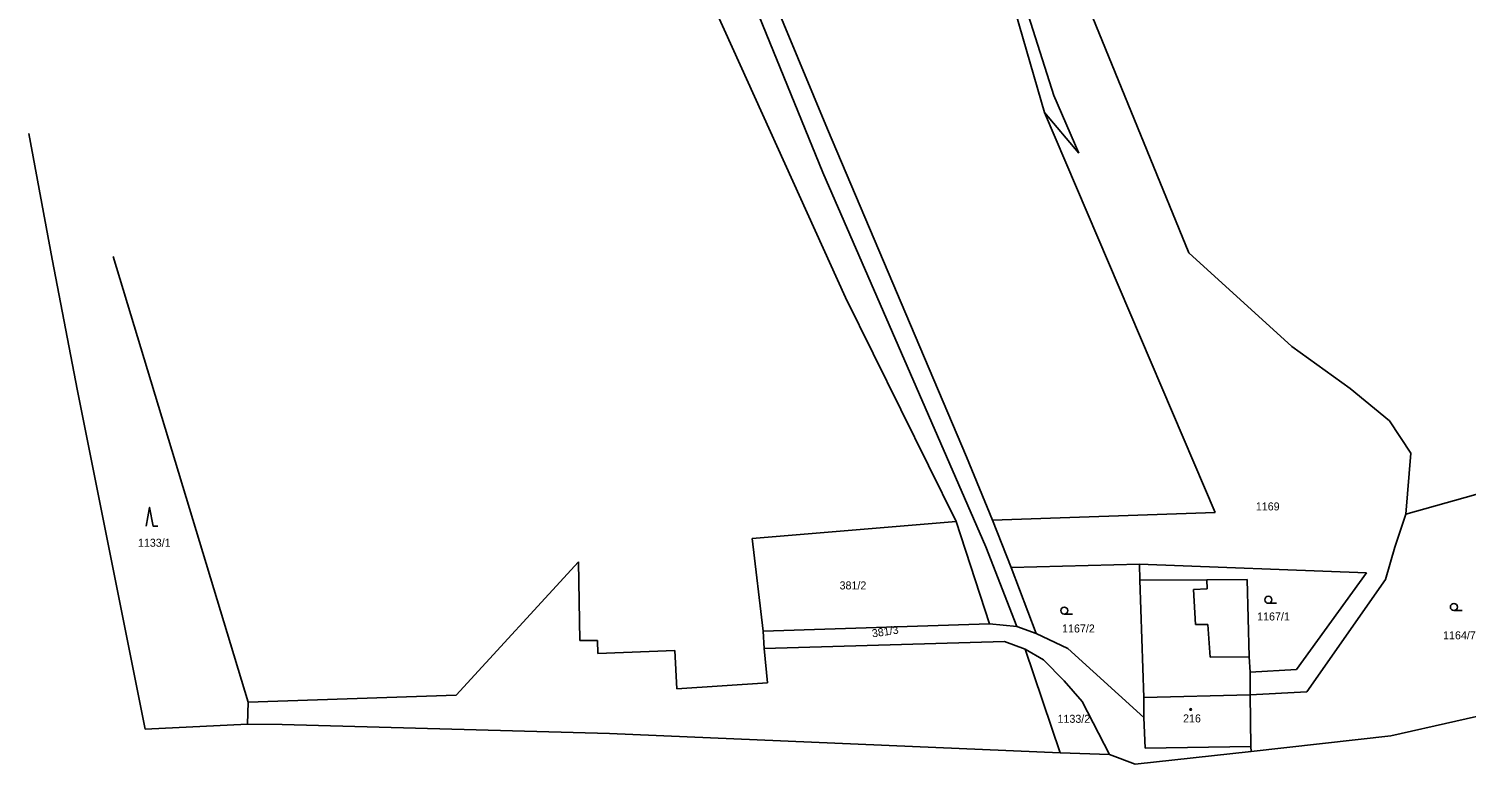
# Model space of a CAD drawing. Extents: x -717507 to -715515, y -957700 to -954941.
# Drawn here: x -717506.6 to -717201.2, y -957384.1 to -957227.8 of the extents above; entities that cross this region are included whole.
import ezdxf

# ---------------------------------------------------------------- set-up
doc = ezdxf.new("R2010")
doc.units = 0
for name, color, linetype in [('Hranice parcel', 7, 'Continuous'), ('Parcelní čísla', 7, 'Continuous'), ('Vnitřní kresba', 7, 'Continuous'), ('Značky budov', 7, 'Continuous'), ('Značky kultur', 7, 'Continuous')]:
    doc.layers.add(name, color=color, linetype=linetype)

msp = doc.modelspace()

# ---------------------------------------------------------------- linework, layer by layer
at = {"layer": 'Hranice parcel'}
for points in [[(-717322.46, -957136.19), (-717288.83, -957241.99)], [(-717358.76, -957196.42), (-717336.91, -957249.12)], [(-717337.93, -957258.37), (-717361.22, -957201.13)], [(-717286.69, -957210.36), (-717260.14, -957275.45)], [(-717363.58, -957217.39), (-717333.07, -957284.89)], [(-717283.49, -957254.25), (-717288.83, -957241.99)], [(-717290.82, -957245.58), (-717254.5, -957330.63)], [(-717290.82, -957245.58), (-717283.49, -957254.25)], [(-717501.64, -957276.8), (-717506.64, -957250.07)], [(-717336.91, -957249.12), (-717307.4, -957318.79)], [(-717303.26, -957337.9), (-717337.93, -957258.37)], [(-717488.7, -957276.21), (-717460.04, -957370.91)], [(-717260.14, -957275.45), (-717238.23, -957295.35)], [(-717501.64, -957276.8), (-717496.27, -957304.76)], [(-717309.53, -957332.5), (-717333.07, -957284.89)], [(-717238.23, -957295.35), (-717225.84, -957304.27)], [(-717496.27, -957304.76), (-717481.9, -957376.62)], [(-717217.47, -957311.1), (-717225.84, -957304.27)], [(-717212.98, -957318), (-717217.47, -957311.1)], [(-717301.85, -957332.24), (-717307.4, -957318.79)], [(-717212.98, -957318), (-717214.03, -957330.99)], [(-717214.03, -957330.99), (-717188.81, -957323.87)], [(-717301.85, -957332.24), (-717254.5, -957330.63)], [(-717214.03, -957330.99), (-717216.34, -957337.97)], [(-717352.88, -957336.16), (-717309.53, -957332.5)], [(-717309.53, -957332.5), (-717302.48, -957354.27)], [(-717297.9, -957342.3), (-717301.85, -957332.24)], [(-717352.88, -957336.16), (-717350.61, -957355.84)], [(-717296.68, -957354.82), (-717303.26, -957337.9)], [(-717218.36, -957344.87), (-717216.34, -957337.97)], [(-717415.84, -957369.43), (-717389.79, -957341.09)], [(-717389.79, -957341.09), (-717389.52, -957357.79)], [(-717297.9, -957342.3), (-717270.64, -957341.59)], [(-717292.59, -957356.35), (-717297.9, -957342.3)], [(-717270.64, -957341.59), (-717270.52, -957345.01)], [(-717270.64, -957341.59), (-717222.38, -957343.42)], [(-717222.38, -957343.42), (-717237.26, -957364)], [(-717270.52, -957345.01), (-717256.29, -957344.89)], [(-717270.52, -957345.01), (-717269.67, -957369.93)], [(-717256.29, -957344.89), (-717247.75, -957344.83)], [(-717247.75, -957344.83), (-717247.32, -957361.26)], [(-717235.07, -957368.7), (-717218.36, -957344.87)], [(-717350.61, -957355.84), (-717302.48, -957354.27)], [(-717350.61, -957355.84), (-717350.33, -957359.5)], [(-717302.48, -957354.27), (-717296.68, -957354.82)], [(-717296.68, -957354.82), (-717292.59, -957356.35)], [(-717389.52, -957357.79), (-717385.76, -957357.82)], [(-717385.76, -957357.82), (-717385.7, -957360.54)], [(-717350.33, -957359.5), (-717299.27, -957358.02)], [(-717299.27, -957358.02), (-717294.88, -957359.61)], [(-717285.84, -957359.49), (-717292.59, -957356.35)], [(-717385.7, -957360.54), (-717369.38, -957359.93)], [(-717369.38, -957359.93), (-717368.92, -957368.08)], [(-717350.33, -957359.5), (-717349.69, -957366.8)], [(-717294.88, -957359.61), (-717287.43, -957381.66)], [(-717294.88, -957359.61), (-717291.03, -957361.93)], [(-717291.03, -957361.93), (-717286.58, -957366.39)], [(-717269.67, -957374.14), (-717285.84, -957359.49)], [(-717247.32, -957361.26), (-717247.08, -957364.56)], [(-717247.08, -957364.56), (-717237.26, -957364)], [(-717247.08, -957364.56), (-717247.08, -957369.32)], [(-717368.92, -957368.08), (-717349.69, -957366.8)], [(-717286.58, -957366.39), (-717282.79, -957370.79)], [(-717460.04, -957370.91), (-717415.84, -957369.43)], [(-717276.99, -957382.02), (-717282.79, -957370.79)], [(-717269.67, -957369.93), (-717269.67, -957374.14)], [(-717247.08, -957369.32), (-717235.07, -957368.7)], [(-717247.08, -957369.32), (-717246.98, -957380.32)], [(-717175.77, -957368.72), (-717217.21, -957378.08)], [(-717269.67, -957374.14), (-717269.42, -957380.68)], [(-717481.9, -957376.62), (-717460.13, -957375.56)], [(-717460.13, -957375.56), (-717452.81, -957375.62)], [(-717383.26, -957377.59), (-717452.81, -957375.62)], [(-717287.43, -957381.66), (-717383.26, -957377.59)], [(-717269.42, -957380.68), (-717246.98, -957380.32)], [(-717246.98, -957380.32), (-717246.91, -957381.4)], [(-717246.91, -957381.4), (-717217.21, -957378.08)], [(-717276.99, -957382.02), (-717287.43, -957381.66)], [(-717276.99, -957382.02), (-717271.5, -957384.1)], [(-717271.5, -957384.1), (-717246.91, -957381.4)]]:
    msp.add_lwpolyline(points, dxfattribs=at)
at = {"layer": 'Vnitřní kresba'}
for points in [[(-717322.46, -957136.19), (-717290.82, -957245.58)], [(-717256.23, -957346.85), (-717256.29, -957344.89)], [(-717259.1, -957346.97), (-717256.23, -957346.85)], [(-717259.1, -957346.97), (-717258.74, -957354.42)], [(-717258.74, -957354.42), (-717256.11, -957354.42)], [(-717256.11, -957354.42), (-717255.62, -957361.32)], [(-717255.62, -957361.32), (-717247.32, -957361.26)], [(-717460.04, -957370.91), (-717460.13, -957375.56)], [(-717269.67, -957369.93), (-717247.08, -957369.32)]]:
    msp.add_lwpolyline(points, dxfattribs=at)
at = {"layer": 'Značky budov'}
msp.add_circle((-717259.74, -957372.46), 0.175, dxfattribs=at)
at = {"layer": 'Značky kultur'}
for points in [[(-717481.7, -957333.54), (-717480.95, -957329.54), (-717480.2, -957333.54), (-717479.2, -957333.54)], [(-717286.59, -957352.2), (-717284.84, -957352.2)], [(-717243.23, -957349.9), (-717241.48, -957349.9)], [(-717203.8, -957351.44), (-717202.05, -957351.44)]]:
    msp.add_lwpolyline(points, dxfattribs=at)
for centre in [(-717243.23, -957349.15), (-717286.59, -957351.45), (-717203.8, -957350.69)]:
    msp.add_circle(centre, 0.75, dxfattribs=at)

# ---------------------------------------------------------------- texts
at = {"layer": 'Parcelní čísla'}
for s, p in [('1169', (-717245.89, -957330.16)), ('1133/1', (-717483.44, -957337.88)), ('381/2', (-717334.34, -957346.95)), ('1167/1', (-717245.61, -957353.55)), ('1167/2', (-717287.06, -957356.1)), ('1164/7', (-717206.1, -957357.55)), ('1133/2', (-717288.03, -957375.29)), ('216', (-717261.35, -957375.21))]:
    msp.add_text(s, height=1.7, dxfattribs=at).set_placement(p)
msp.add_text('381/3', height=1.7, rotation=8.5001, dxfattribs=at).set_placement((-717327.34, -957357.16))

doc.saveas('drawing.dxf')
